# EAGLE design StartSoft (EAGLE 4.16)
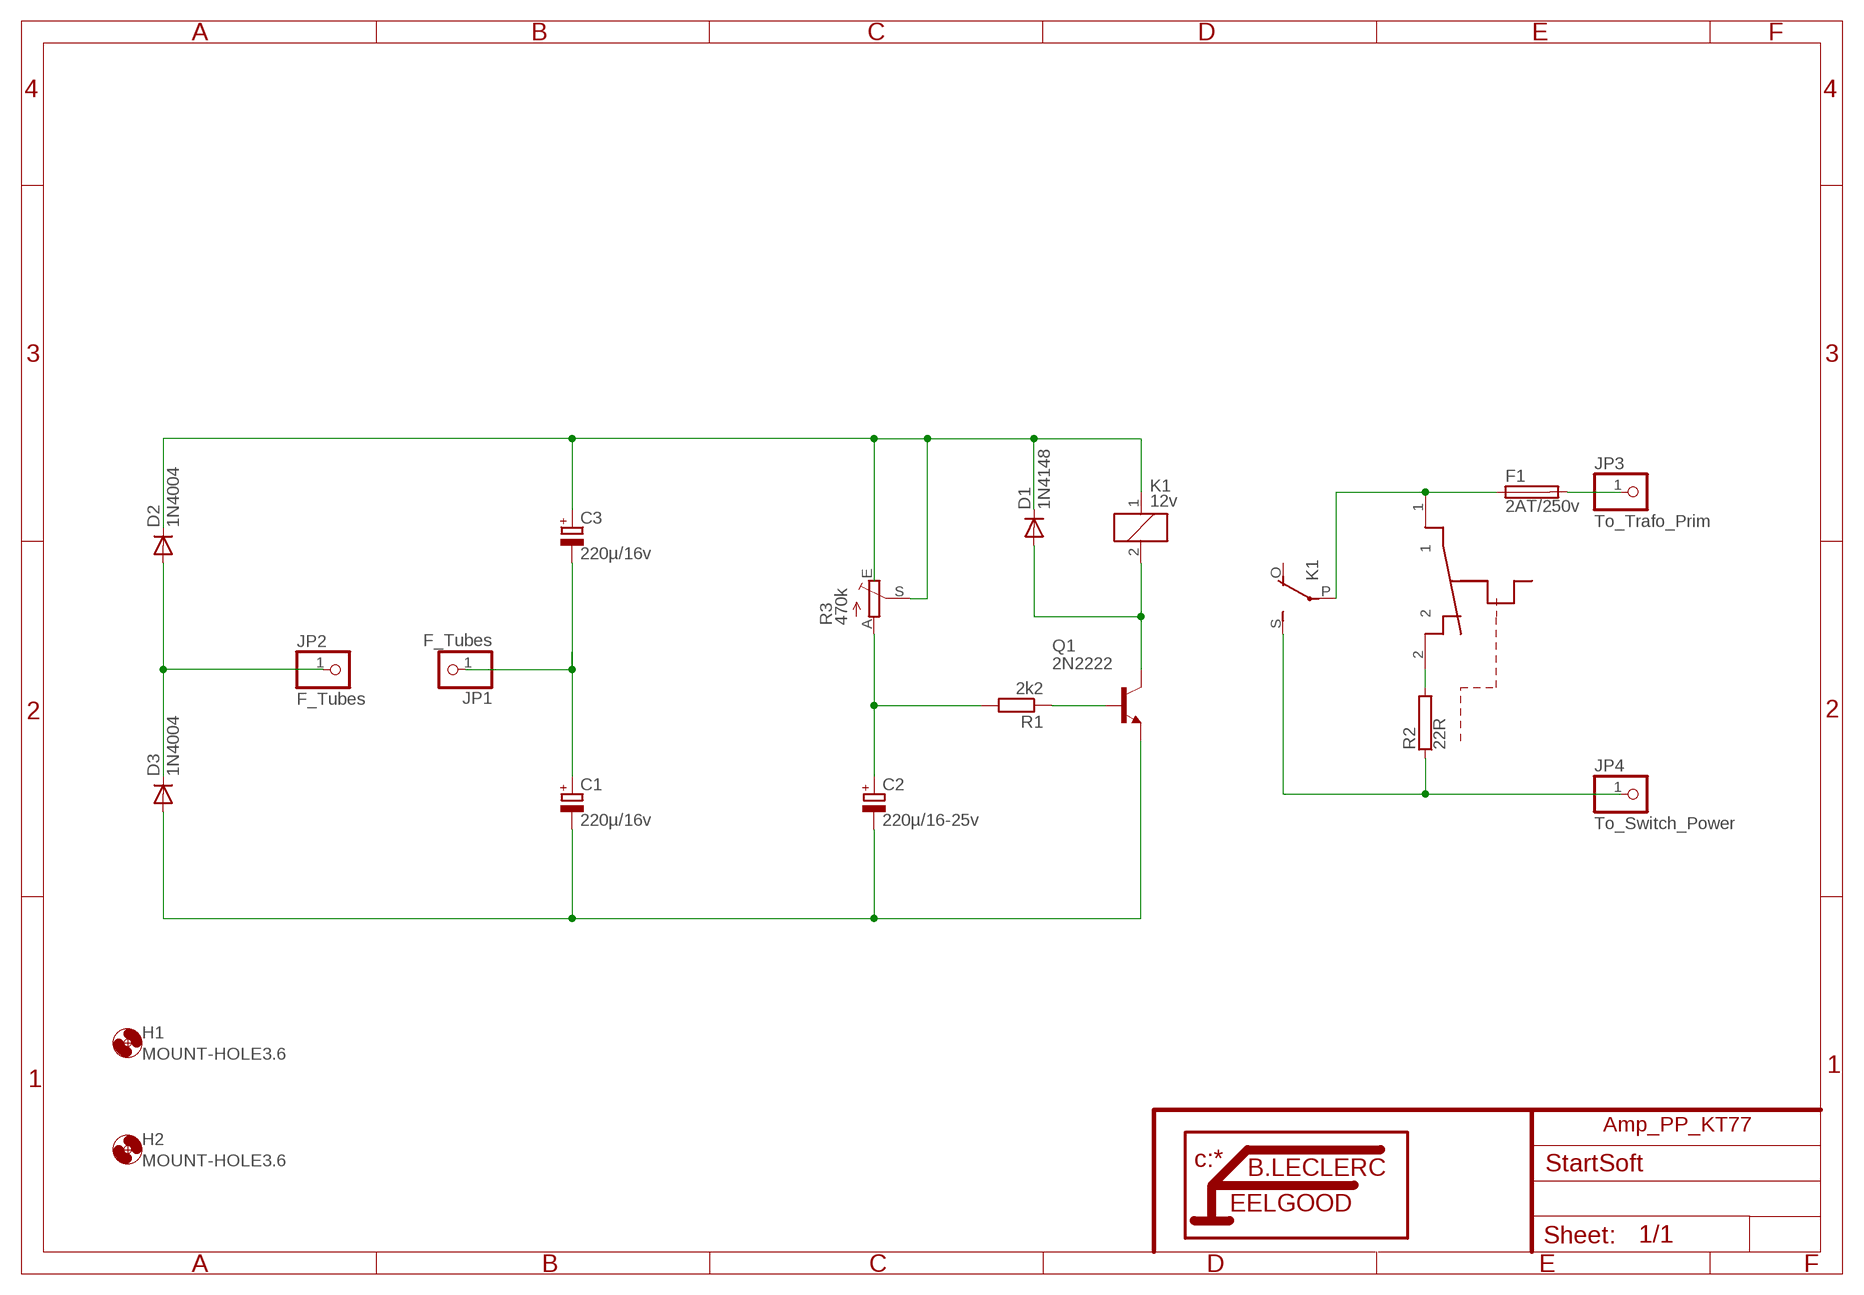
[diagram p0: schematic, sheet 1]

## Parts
C1  220µ/16v  CPOL-EUE5-8.5  [E5-8,5]
C2  220µ/16-25v  CPOL-EUE5-8.5  [E5-8,5]
C3  220µ/16v  CPOL-EUE5-8.5  [E5-8,5]
D1  1N4148  [DO35-10]
D2  1N4004  [DO41-10]
D3  1N4004  [DO41-10]
F1  2AT/250v  FUSESH22,5  [SH22,5]
H1  MOUNT-HOLE3.6  [3,6]
H2  MOUNT-HOLE3.6  [3,6]
JP1  F_Tubes  PINHD-1X1  [1X01]
JP2  F_Tubes  PINHD-1X1  [1X01]
JP3  To_Trafo_Prim  PINHD-1X1  [1X01]
JP4  To_Switch_Power  PINHD-1X1  [1X01]
K1  12v  G2R  [G2R]
Q1  2N2222  [TO18]
R1  2k2  R-EU_0309/12  [0309/12]
R2  22R  RKH208-8  [KH208-8]
R3  470k  TRIM_EU-LI10  [LI10]
TH1  INTERTHERMIC  [INTERTHERMIC]

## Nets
GND: C1.- C2.- D3.A Q1.1(E)
N$1: D2.A D3.C JP2.1
N$2: C1.+ C3.- JP1.1
N$4: C3.+ D1.C D2.C K1.1 R3.E R3.S
N$5: D1.A K1.2 Q1.3(C)
N$6: C2.+ R1.2 R3.A
N$8: Q1.2(B) R1.1
N$9: F1.1 K1.P(2:P) TH1.1
N$10: JP4.1 K1.S(2:S) R2.1
N$31: R2.2 TH1.2
N$43: F1.2 JP3.1
Unconnected: K1.O(2:O)

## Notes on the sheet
- Amp_PP_KT77

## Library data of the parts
C1-C3 = rcl:CPOL-EU: POLARIZED CAPACITOR, European symbol
D1 = diode:1N4148: DIODE
D2 D3 = diode:1N4004: DIODE
F1 = fuse:FUSE: Fuse
H1 H2 = holes:MOUNT-HOLE: MOUNTING HOLE with drill center marker
JP1-JP4 = pinhead:PINHD-1X1: PIN HEADER
K1 = relay:G2R: RELAY 1 x switch, Omron
Q1 = transistor-npn:2N2222*: NPN Transistor
R1 = rcl:R-EU_: RESISTOR, European symbol
R2 = resistor-power:R: Power Resitor
R3 = pot:TRIM_EU-: POTENTIOMETER
TH1 = special:INTERTHERMIC

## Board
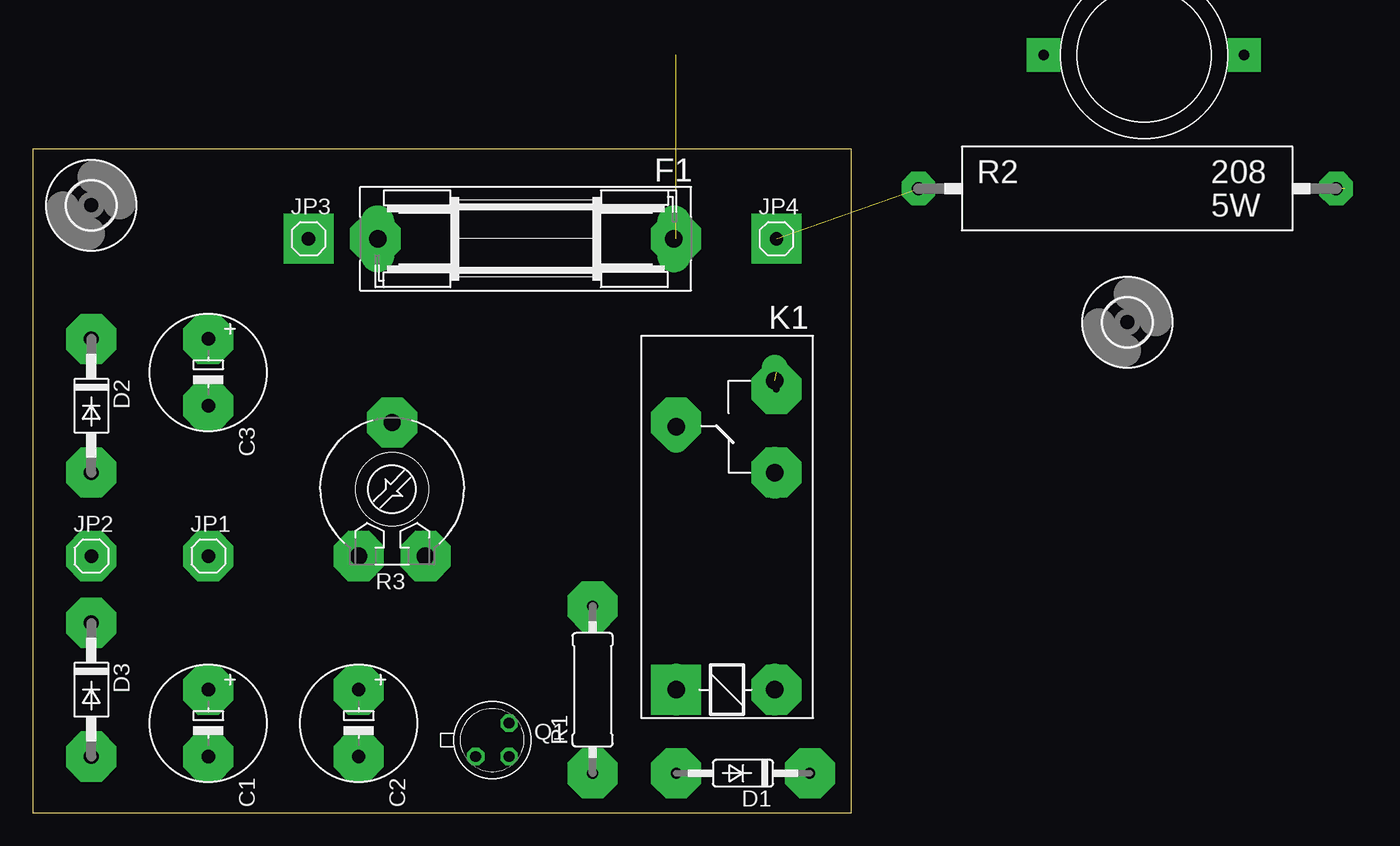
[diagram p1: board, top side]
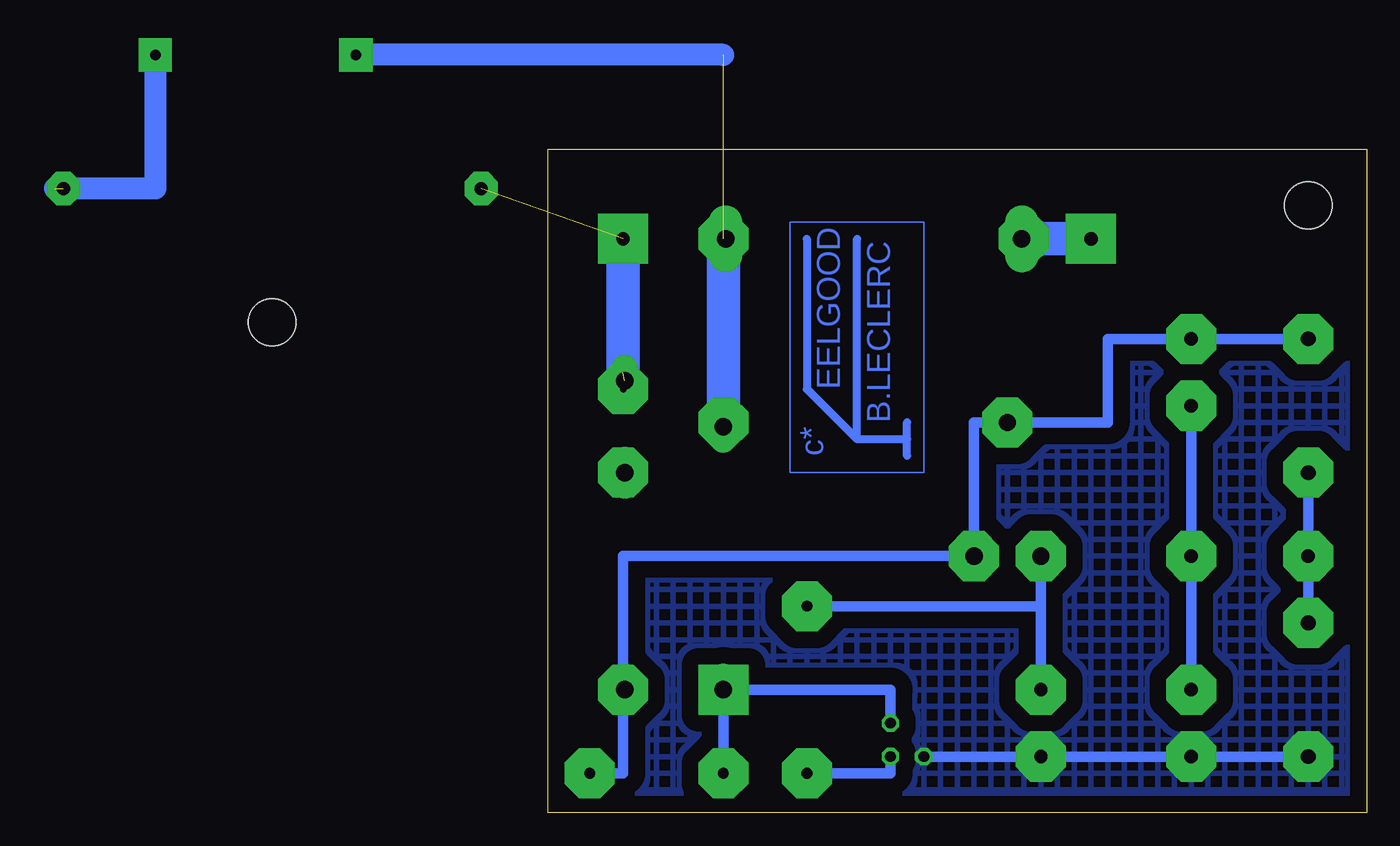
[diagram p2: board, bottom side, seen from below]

Size 62.21 x 50.47 mm. Coordinates in mm from the lower left corner, seen from the top.
Outline: 0,0 62.21,0 62.21,50.47 0,50.47 0,0
Copper layers (1*16): Top 0.035mm / dielectric 1.5mm / Bottom 0.035mm
Design rules "default": minimum track width 10mil, minimum drill 24mil, track to track 8mil, track to pad 8mil, pad to pad 8mil, via to via 8mil, smd to smd 8mil, copper to edge 40mil, drill to drill 8mil, minimum pad ring 10mil, minimum via ring 8mil, stop-mask expansion 4mil, vias tented up to drill 0mil, thermal gap 10mil

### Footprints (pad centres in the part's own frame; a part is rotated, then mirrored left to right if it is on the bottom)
E5-8,5 = drill 1.016 pad 2.54 round: + -2.54,0 | drill 1.016 pad 2.54 octagon: - 2.54,0
DO35-10 = drill 0.813 long: A 5.08,0; C -5.08,0
DO41-10 = drill 1.118 round: A 5.08,0; C -5.08,0
SH22,5 = drill 1.321 pad 2.54 long: 1 -11.252,0; 2 11.252,0
3,6 = hole 3.6: 0,0
1X01 = drill 1.016 octagon: 1 0,0
G2R = drill 1.321 long: 1 -2.54,-3.683; 2 -2.54,3.81; O 13.97,-3.683; P 17.45,3.81; S 20.955,-3.683
TO18 = drill 0.813 octagon: 1 -1.27,-1.27; 2 1.27,-1.27; 3 1.27,1.27
0309/12 = drill 0.813 octagon: 1 -6.35,0; 2 6.35,0
KH208-8 = drill 1.016 pad 2.54 octagon: 1 -15.875,0; 2 15.875,0
LI10 = drill 1.321 octagon: A -2.54,-5.08; E 2.54,-5.08; S 0,5.08
INTERTHERMIC = drill 0.8 pad 2.54 square: 1 -7.62,0; 2 7.62,0

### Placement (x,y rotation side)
C1  13.33,6.82 270 top
C2  24.76,6.82 270 top
C3  13.33,33.49 270 top
D1  53.97,3.01 180 top
D2  4.44,30.95 270 top
D3  4.44,9.36 270 top
F1  37.46,43.65 180 top
H1  4.44,46.19 0 top
H2  not placed on the board
JP1  13.33,19.52 0 top
JP2  4.44,19.52 0 top
JP3  20.95,43.65 0 top
JP4  56.51,43.65 0 top
K1  52.7,11.9 90 top
Q1  34.92,5.55 0 top
R1  42.54,9.36 90 top
R2  not placed on the board
R3  27.3,24.6 0 top
TH1  84.45,57.62 0 top  (outside the outline)
U$2  [LITTFEEL]  31.11,28.41 90 bottom

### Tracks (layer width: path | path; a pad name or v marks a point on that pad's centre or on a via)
GND  (via drill 0.5 pad 3.81)
  Bottom 0.813: D3.A C1.- C2.- Q1.1
  other vias: 24.76,4.28 13.33,4.28 4.44,4.28
  pour Bottom (isolate 1.27, no thermals, hatched): 0.63,50 14.6,50 14.6,39.84 14.6,38.57 27.3,38.57 43.81,22.06 61.59,22.06 61.59,0.47 0.63,0.47
N$1
  Bottom 0.813: D3.C JP2.1 D2.A
N$2
  Bottom 0.813: C3.- JP1.1 C1.+
N$3  (via drill 0.6 pad 3.81)
  other vias: 26.03,43.65
N$4
  Bottom 0.813: D2.C C3.+ 19.68,36.03 19.68,29.68 R3.S 29.84,29.68 R3.E 56.51,19.52 56.51,9.36 | 56.51,9.36 K1.1 | 56.51,9.36 56.51,3.01 D1.C
N$5
  Bottom 0.813: D1.A K1.2 36.19,9.36 Q1.3
N$6
  Bottom 0.813: C2.+ 24.76,15.71 | 24.76,15.71 R3.A | 24.76,15.71 R1.2
N$7  (via drill 0.5 pad 3.81)
  other vias: 20.95,43.65
N$8
  Bottom 0.813: R1.1 36.19,3.01 Q1.2
N$9  (1 unrouted)
  Bottom 1.676: 48.89,57.62 TH1.1
  Bottom 2.54: F1.1 48.89,43.65 K1.P
N$10  (2 unrouted)
  Bottom 2.54: JP4.1 56.51,33.49 56.51,32.22
N$11  (via drill 0.5 pad 3.81)
  other vias: 48.89,9.36
N$12  (via drill 0.5 pad 3.81)
  other vias: 42.54,3.01
N$13  (via drill 0.6 pad 3.81)
  other vias: 48.89,43.65
N$14  (via drill 0.5 pad 3.81)
  other vias: 29.84,19.52
N$15  (via drill 0.5 pad 3.81)
  other vias: 24.76,19.52
N$16  (via drill 0.5 pad 3.81)
  other vias: 13.33,9.36
N$17  (via drill 0.5 pad 3.81)
  other vias: 27.3,29.68
N$18  (via drill 0.5 pad 3.81)
  other vias: 24.76,9.36
N$19  (via drill 0.5 pad 3.81)
  other vias: 42.54,15.71
N$20  (via drill 0.5 pad 3.81)
  other vias: 56.51,9.36
N$21  (via drill 0.5 pad 3.81)
  other vias: 59.05,3.01
N$22  (via drill 0.5 pad 3.81)
  other vias: 48.89,3.01
N$23  (via drill 0.5 pad 3.81)
  other vias: 4.44,19.52
N$24  (via drill 0.5 pad 3.81)
  other vias: 4.44,36.03
N$25  (via drill 0.5 pad 3.81)
  other vias: 13.33,19.52
N$26  (via drill 0.5 pad 3.81)
  other vias: 4.44,25.87
N$27  (via drill 0.5 pad 3.81)
  other vias: 13.33,30.95
N$28  (via drill 0.5 pad 3.81)
  other vias: 13.33,36.03
N$29  (via drill 0.5 pad 3.81)
  other vias: 4.44,14.44
N$30  (via drill 0.6 pad 3.81)
  other vias: 56.51,43.65
N$31  (1 unrouted)
  Bottom 1.676: TH1.2 92.07,47.46 99.69,47.46
N$33  (via drill 0.5 pad 3.81)
  other vias: 48.89,29.68
N$34  (via drill 0.5 pad 3.81)
  other vias: 56.51,43.65
N$35  (via drill 0.5 pad 3.81)
  other vias: 56.51,25.87
N$36  (via drill 0.5 pad 3.81)
  other vias: 56.51,32.22
N$43
  Bottom 2.54: JP3.1 F1.2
